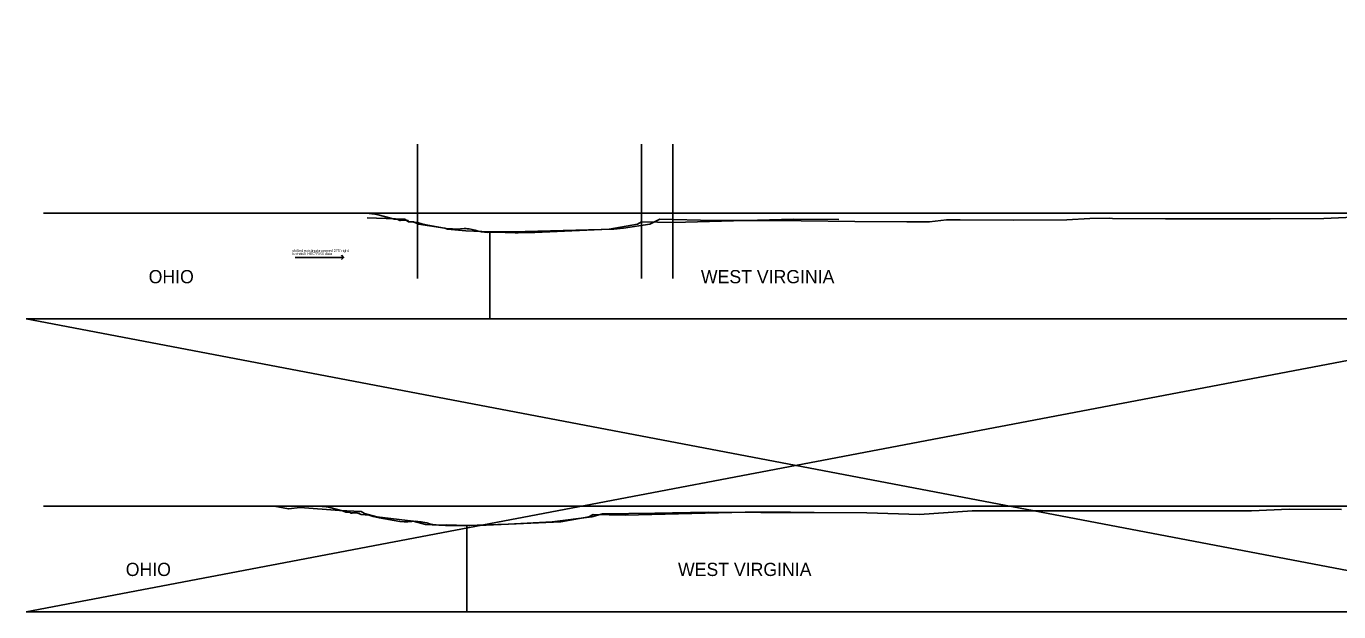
# Model space of a CAD drawing. Extents: x -9489 to 16720, y -4790 to 1662.
# Drawn here: x -9489 to -2037, y -4790 to -1466 of the extents above; entities that cross this region are included whole.
import ezdxf

# ---------------------------------------------------------------- set-up
doc = ezdxf.new("R2010")
doc.units = 0
for name, color, linetype in [('MD_P_Surface_Finished_Grade', 7, 'Continuous'), ('PF_P_Grade_Line', 7, 'Continuous'), ('PF_X_Ground_Line', 7, 'Continuous'), ('SC_Scratch1', 7, 'Continuous')]:
    doc.layers.add(name, color=color, linetype=linetype)

msp = doc.modelspace()

# ---------------------------------------------------------------- linework, layer by layer
at = {"layer": 'MD_P_Surface_Finished_Grade'}
msp.add_lwpolyline([(-7698.8, -2766.5), (-7687, -2779.3), (-7699.8, -2791.2)], dxfattribs=at)
at = {"layer": 'PF_P_Grade_Line'}
for p, q in [((-7266.9, -2134.8), (-7266.9, -2898.7)), ((-5995.3, -2134.8), (-5995.3, -2898.7)), ((-5817.6, -2134.8), (-5817.6, -2898.7)), ((-752.6, -3128.2), (-9488.8, -4790.1)), ((-752.6, -4790.1), (-9488.8, -3128.2))]:
    msp.add_line(p, q, dxfattribs=at)
at = {"layer": 'PF_X_Ground_Line'}
msp.add_line((-7962, -2779.3), (-7687, -2779.3), dxfattribs=at)
for points in [[(-7369, -2568.8), (-7365.5, -2567.7), (-7362.5, -2567.4), (-7348.2, -2567.2), (-7333.6, -2567.4), (-7322, -2568.6), (-7321.7, -2572.2)], [(-7644, -4230.7), (-7640.5, -4229.5), (-7637.5, -4229.3), (-7623.2, -4229), (-7608.6, -4229.3), (-7597, -4230.4), (-7596.7, -4234.1)]]:
    msp.add_lwpolyline(points, dxfattribs=at)
at = {"layer": 'SC_Scratch1'}
for p, q in [((-9391.8, -2528.2), (-836.4, -2528.2)), ((-6857.6, -2634.2), (-6857.6, -3128.2)), ((-9391.8, -4190.1), (-772.7, -4190.1)), ((-6987.6, -4301.1), (-6987.6, -4790.1))]:
    msp.add_line(p, q, dxfattribs=at)
for points in [[(-752.6, -1466.4), (-752.6, -3128.2), (-9488.8, -3128.2)], [(-7558.9, -2528.2), (-7510, -2533.6), (-7490.4, -2537), (-7418.2, -2555.5), (-7399.8, -2562.2), (-7388.4, -2562.3), (-7378.1, -2563.7), (-7368.4, -2569.2), (-7364.1, -2568.3), (-7362.5, -2567.8), (-7348.2, -2567.4), (-7333.6, -2568), (-7326.3, -2570.3), (-7321.7, -2572.2), (-7312.1, -2576.1), (-7266.9, -2579.8), (-7243.4, -2588.2), (-7209.5, -2595.7), (-7093.2, -2615.7), (-7068.3, -2617.3), (-7046.7, -2618.6), (-7002.1, -2614.5), (-6990.8, -2615), (-6983.6, -2617.1), (-6973.2, -2617), (-6939.9, -2623.1), (-6923.6, -2629.1), (-6905.2, -2633.8), (-6868.2, -2636.8), (-6827.2, -2635.8), (-6712.6, -2639.3), (-6695.7, -2639.2), (-6601.9, -2636.7), (-6178.6, -2617.7), (-6018.8, -2590.3), (-5995.3, -2575.9), (-5813.3, -2580.2), (-5131.6, -2562.1), (-4875.3, -2563.6)], [(-1831.6, -2545.2), (-2120.6, -2557.2), (-2425.6, -2559.7), (-2721.6, -2560.2), (-3020.6, -2560.2), (-3321.6, -2557.2), (-3340.6, -2556.7), (-3450.6, -2557.7), (-3580.6, -2565.7), (-3883.6, -2567.2), (-4185.6, -2566.2), (-4263.6, -2565.2), (-4360.6, -2575.7), (-4489.6, -2577.2), (-4783.6, -2574.2), (-5089.6, -2570.2), (-5288.6, -2569.2), (-5582.6, -2568.7), (-5891.6, -2561.2), (-5948.6, -2589.2), (-6098.1, -2612.2), (-6152.6, -2618.2), (-6727.6, -2633.2), (-6857.6, -2634.2), (-6992.6, -2628.2), (-7097.6, -2618.2), (-7112.1, -2612.2), (-7261.6, -2589.2), (-7290.6, -2576.2), (-7317.6, -2576.2), (-7339.6, -2561.2), (-7356.6, -2561.2), (-7392.6, -2560.2), (-7552.6, -2553.2)], [(-752.6, -3128.2), (-752.6, -4790.1), (-9488.8, -4790.1)], [(-2020.6, -4210.6), (-2318.6, -4208.6), (-2532.6, -4218.1), (-4118.6, -4218.1), (-4416.6, -4237.1), (-4715.6, -4229.1), (-5014.6, -4227.1), (-5317.6, -4226.1), (-5617.6, -4225.6), (-5920.6, -4230.6), (-6217.6, -4235.1), (-6276.6, -4251.6), (-6502.6, -4280.1), (-6752.6, -4293.1), (-6987.6, -4301.1), (-7107.6, -4300.1), (-7222.6, -4294.1), (-7292.6, -4275.1), (-7497.6, -4251.6), (-7567.6, -4232.1), (-7587.6, -4220.1), (-7709.6, -4215.1), (-7933.6, -4198.1), (-8000.6, -4206.1), (-8081.6, -4190.1)], [(-7833.9, -4190.1), (-7785, -4195.4), (-7765.4, -4198.8), (-7693.2, -4217.4), (-7674.8, -4224.1), (-7663.4, -4224.1), (-7653.1, -4225.6), (-7643.4, -4231.1), (-7639.1, -4230.2), (-7637.5, -4229.6), (-7623.2, -4229.3), (-7608.6, -4229.9), (-7601.3, -4232.2), (-7596.7, -4234.1), (-7587.1, -4238), (-7541.9, -4241.7), (-7518.4, -4250.1), (-7484.5, -4257.5), (-7368.2, -4277.5), (-7343.3, -4279.2), (-7321.7, -4280.4), (-7277.1, -4276.4), (-7265.8, -4276.9), (-7258.6, -4278.9), (-7248.2, -4278.9), (-7214.9, -4284.9), (-7198.6, -4291), (-7180.2, -4295.6), (-7143.2, -4298.7), (-7102.2, -4297.6), (-6987.6, -4301.1), (-6970.7, -4301), (-6876.9, -4298.6), (-6453.6, -4279.5), (-6293.8, -4252.1), (-6270.3, -4237.7), (-6088.3, -4242.1), (-5406.6, -4224), (-5150.3, -4225.4)]]:
    msp.add_lwpolyline(points, dxfattribs=at)

# ---------------------------------------------------------------- texts
at = {"layer": 'MD_P_Surface_Finished_Grade'}
for s, height, p in [('to match HEC-RAS data', 15, (-7977.9, -2764.3)), ("shifted existing/proposed 275' right", 15, (-7977.9, -2747.3)), ('OHIO', 75, (-8793.8, -2925.3)), ('WEST VIRGINIA', 75, (-5658.2, -2925.3)), ('OHIO', 75, (-8923.8, -4587.2)), ('WEST VIRGINIA', 75, (-5788.2, -4587.2))]:
    msp.add_text(s, height=height, dxfattribs=at).set_placement(p)

doc.saveas('drawing.dxf')
